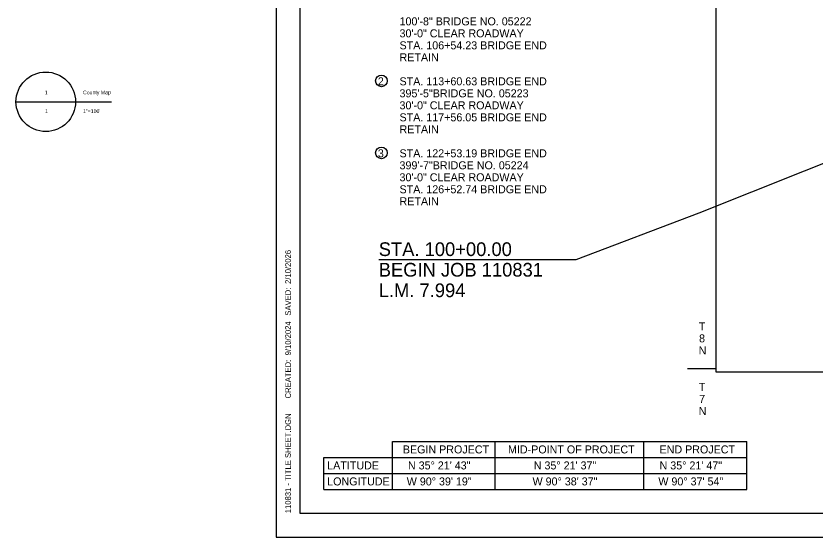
# Model space of a CAD drawing. Extents: x -0.25 to 1.92, y 0 to 0.95.
# Drawn here: x -0.227 to 0.472, y 0 to 0.456 of the extents above; entities that cross this region are included whole.
import ezdxf

# ---------------------------------------------------------------- set-up
doc = ezdxf.new("R2010")
doc.units = 0
for name, color, linetype in [('Default', 7, 'Continuous'), ('DSN_DRFT_DNC', 7, 'Continuous'), ('DSN_DRFT_Guideline-No-Plot', 7, 'Continuous'), ('SHET_Annotations', 7, 'Continuous'), ('SHET_Border-Lines', 7, 'Continuous'), ('SHET_Border-Text', 7, 'Continuous')]:
    doc.layers.add(name, color=color, linetype=linetype)

msp = doc.modelspace()

# ---------------------------------------------------------------- linework, layer by layer
at = {"layer": 'Default'}
for p, q in [((-0.22744, 0.38096), (-0.17536, 0.38096)), ((-0.20117, 0.38096), (-0.14385, 0.38096)), ((0.26223, 0.24279), (0.3699, 0.28371)), ((0.08973, 0.24279), (0.26223, 0.24279))]:
    msp.add_line(p, q, dxfattribs=at)
msp.add_lwpolyline([(0.3699, 0.28371), (0.60176, 0.37631), (0.53442, 0.3581)], dxfattribs=at)
msp.add_circle((-0.2014, 0.38096), 0.02604, dxfattribs=at)
at = {"layer": 'DSN_DRFT_DNC'}
msp.add_lwpolyline([(0.38477, 0.54167), (1.0319, 0.54167), (1.0319, 0.1443), (0.38477, 0.1443)], close=True, dxfattribs=at)
at = {"layer": 'DSN_DRFT_Guideline-No-Plot'}
msp.add_lwpolyline([(0, 0), (1.41667, 0), (1.41667, 0.91667), (0, 0.91667)], close=True, dxfattribs=at)
at = {"layer": 'SHET_Annotations'}
msp.add_line((0.35977, 0.14738), (0.38477, 0.14738), dxfattribs=at)
for centre in [(0.09208, 0.39927), (0.09208, 0.33627)]:
    msp.add_circle(centre, 0.00509, dxfattribs=at)
at = {"layer": 'SHET_Border-Lines'}
msp.add_lwpolyline([(0.02083, 0.02083), (1.39583, 0.02083), (1.39583, 0.89583), (0.02083, 0.89583)], close=True, dxfattribs=at)
at = {"layer": 'SHET_Border-Text'}
for p, q in [((0.10167, 0.04167), (0.10167, 0.08367)), ((0.10167, 0.08367), (0.41167, 0.08367)), ((0.19167, 0.04167), (0.19167, 0.08367)), ((0.32167, 0.04167), (0.32167, 0.08367)), ((0.41167, 0.04167), (0.41167, 0.08367)), ((0.04167, 0.04167), (0.04167, 0.06967)), ((0.04167, 0.06967), (0.41167, 0.06967)), ((0.04167, 0.05567), (0.41167, 0.05567)), ((0.04167, 0.04167), (0.41167, 0.04167))]:
    msp.add_line(p, q, dxfattribs=at)

# ---------------------------------------------------------------- texts
at = {"layer": 'Default'}
for s, height, p in [('1', 0.00328, (-0.20225, 0.38752)), ('County Map', 0.003281, (-0.16885, 0.38752)), ('1', 0.00328, (-0.20202, 0.37112)), ('1"=100\'', 0.003281, (-0.16885, 0.37112)), ('STA. 100+00.00', 0.012, (0.08973, 0.24595)), ('BEGIN JOB 110831', 0.012, (0.08973, 0.22795)), ('L.M. 7.994', 0.012, (0.08973, 0.20995))]:
    msp.add_text(s, height=height, dxfattribs=at).set_placement(p)
at = {"layer": 'SHET_Annotations'}
for s, p in [('100\'-8" BRIDGE NO. 05222', (0.10792, 0.44788)), ('30\'-0" CLEAR ROADWAY', (0.10792, 0.43738)), ('STA. 106+54.23 BRIDGE END', (0.10792, 0.42688)), ('RETAIN', (0.10792, 0.41638)), ('2', (0.08896, 0.39538)), ('STA. 113+60.63 BRIDGE END', (0.10792, 0.39538)), ('395\'-5"BRIDGE NO. 05223', (0.10792, 0.38488)), ('30\'-0" CLEAR ROADWAY', (0.10792, 0.37438)), ('STA. 117+56.05 BRIDGE END', (0.10792, 0.36388)), ('RETAIN', (0.10792, 0.35338)), ('3', (0.08896, 0.33238)), ('STA. 122+53.19 BRIDGE END', (0.10792, 0.33238)), ('399\'-7"BRIDGE NO. 05224', (0.10792, 0.32188)), ('30\'-0" CLEAR ROADWAY', (0.10792, 0.31138)), ('STA. 126+52.74 BRIDGE END', (0.10792, 0.30088)), ('RETAIN', (0.10792, 0.29038)), ('T', (0.36963, 0.18088)), ('8', (0.36983, 0.17038)), ('N', (0.36947, 0.15988)), ('T', (0.36963, 0.12788)), ('7', (0.3699, 0.11738)), ('N', (0.36947, 0.10688)), ('N 35° 21\' 43"', (0.11529, 0.05917)), ('N 35° 21\' 37"', (0.22529, 0.05917)), ('N 35° 21\' 47"', (0.33529, 0.05917)), ('W 90° 39\' 19"', (0.11423, 0.04517)), ('W 90° 38\' 37"', (0.22423, 0.04517)), ('W 90° 37\' 54"', (0.33423, 0.04517))]:
    msp.add_text(s, height=0.007, dxfattribs=at).set_placement(p)
at = {"layer": 'SHET_Border-Text'}
for s, p in [('2/10/2026', (0.01292, 0.22154)), ('2/10/2026', (0.01292, 0.22154)), ('  SAVED: ', (0.01292, 0.19009)), ('  SAVED: ', (0.01292, 0.19009)), ('9/10/2024', (0.01292, 0.15903)), ('9/10/2024', (0.01292, 0.15903)), ('     CREATED: ', (0.01292, 0.11206)), ('     CREATED: ', (0.01292, 0.11206)), ('110831 - TITLE SHEET.DGN', (0.01292, 0.02083)), ('110831 - TITLE SHEET.DGN', (0.01292, 0.02083))]:
    msp.add_text(s, height=0.005, rotation=90, dxfattribs=at).set_placement(p)
for s, p in [('BEGIN PROJECT', (0.11082, 0.07317)), ('MID-POINT OF PROJECT', (0.20277, 0.07317)), ('END PROJECT', (0.33526, 0.07317)), ('LATITUDE', (0.04467, 0.05917)), ('LONGITUDE', (0.04467, 0.04517))]:
    msp.add_text(s, height=0.007, dxfattribs=at).set_placement(p)

doc.saveas('drawing.dxf')
